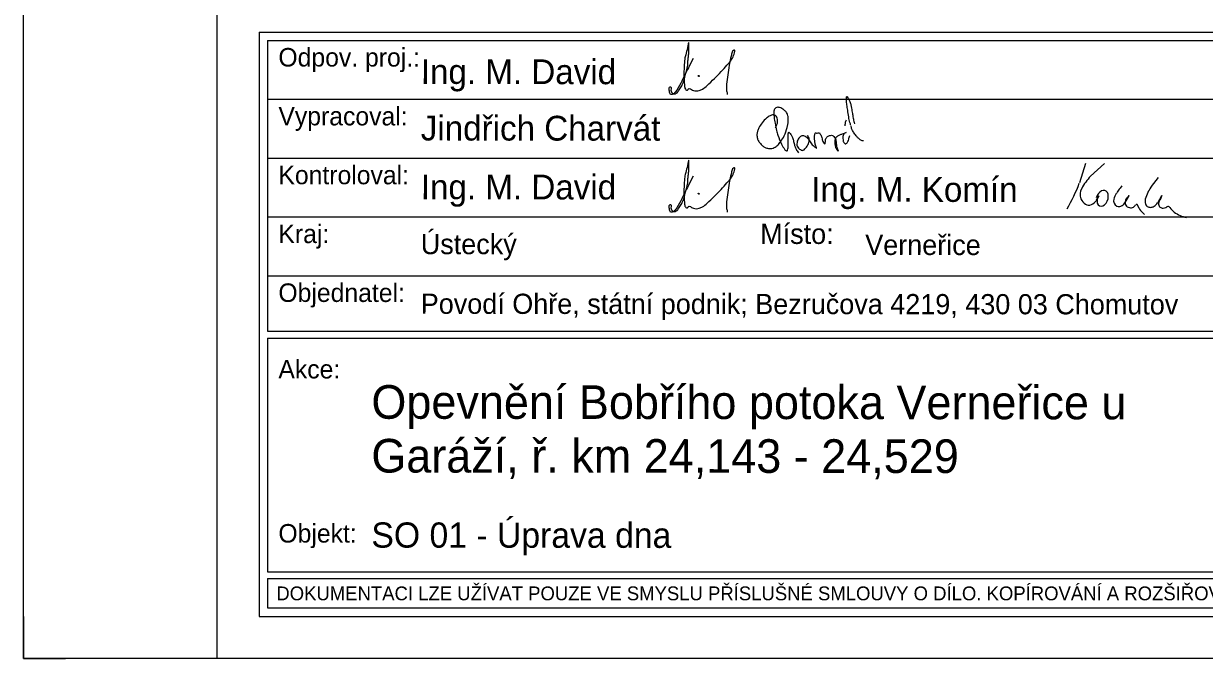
# Model space of a CAD drawing. Extents: x 67.3 to 115.4, y -93.9 to -78.3.
# Drawn here: x 79.77 to 86.79, y -93.93 to -90.16 of the extents above; entities that cross this region are included whole.
import ezdxf

# ---------------------------------------------------------------- set-up
doc = ezdxf.new("R2010")
doc.units = 0
for name, color, linetype in [('07_rozpiska', 7, 'Continuous'), ('07_rámeček', 7, 'Continuous'), ('Default', 7, 'Continuous'), ('Rozpiska + rámeček', 7, 'Continuous')]:
    doc.layers.add(name, color=color, linetype=linetype)

# ---------------------------------------------------------------- blocks, each defined once
blk = doc.blocks.new('Charvat')
at = {"layer": 'Rozpiska + rámeček'}
for points in [[(0.0826, 0.02), (0.0817, 0.0228), (0.0806, 0.0281), (0.0796, 0.0345), (0.0789, 0.0395), (0.0784, 0.0445), (0.0784, 0.0456), (0.0785, 0.0469), (0.0787, 0.0476), (0.0791, 0.0473), (0.0804, 0.0456), (0.0816, 0.0427), (0.0827, 0.0394), (0.0832, 0.0363), (0.0841, 0.0314), (0.0846, 0.0282), (0.0855, 0.0238), (0.086, 0.0216)], [(0.0108, 0.0178), (0.0123, 0.0208), (0.0129, 0.0234), (0.0122, 0.0279), (0.0108, 0.0294), (0.0087, 0.0301), (0.0059, 0.0293), (0.0024, 0.0271), (-0.0017, 0.0225), (-0.0049, 0.0177), (-0.0062, 0.0145), (-0.0067, 0.0115), (-0.0063, 0.0075), (-0.0059, 0.0064), (-0.0039, 0.0034), (-0.0014, 0.0007), (0.001, -0.001), (0.0043, -0.0019), (0.0075, -0.0019), (0.0097, -0.001), (0.0131, 0.0013), (0.0158, 0.0045), (0.0192, 0.0101), (0.022, 0.0182), (0.0223, 0.0193), (0.023, 0.0256), (0.0227, 0.0293), (0.0219, 0.0315), (0.0199, 0.034), (0.017, 0.036), (0.0147, 0.0371), (0.0142, 0.0372), (0.013, 0.0373), (0.0113, 0.0368), (0.0106, 0.0362), (0.0097, 0.0348), (0.0095, 0.0343), (0.0093, 0.0333), (0.0093, 0.0314), (0.0096, 0.0279), (0.0105, 0.0221), (0.012, 0.0151), (0.0133, 0.0108), (0.0166, 0.0023), (0.0195, -0.0026), (0.0202, -0.0035), (0.0214, -0.0042), (0.022, -0.0042), (0.0225, -0.0034), (0.023, -0.0014), (0.0231, 0), (0.0231, 0.0051), (0.0231, 0.0111), (0.0231, 0.0124), (0.0233, 0.0132), (0.0236, 0.0135), (0.024, 0.0133), (0.0254, 0.0115), (0.0268, 0.0092), (0.0279, 0.0059), (0.0289, 0.0018), (0.0298, -0.0012), (0.0315, -0.0041), (0.0327, -0.0059)], [(0.0771, 0.0198), (0.0779, 0.024), (0.0784, 0.0252)], [(0.0428, 0.0062), (0.0417, 0.0075), (0.0401, 0.009), (0.0394, 0.0095), (0.0378, 0.0101), (0.0368, 0.0101), (0.0353, 0.0098), (0.034, 0.0088), (0.0326, 0.0071), (0.0316, 0.0051), (0.0313, 0.0026), (0.0313, 0.0011), (0.0322, -0.0007), (0.0338, -0.0025), (0.0354, -0.0034), (0.0366, -0.0037), (0.0381, -0.0031), (0.0397, -0.0014), (0.0411, 0.0004), (0.0422, 0.0025), (0.043, 0.005), (0.043, 0.0063), (0.0429, 0.0069), (0.0424, 0.0086), (0.0414, 0.0106), (0.0421, 0.009), (0.0433, 0.0053), (0.0444, 0.0034), (0.0458, 0.0017), (0.0476, 0), (0.0497, -0.0015), (0.0498, -0.0016), (0.0499, -0.0016), (0.0499, -0.0014), (0.0492, 0.0003), (0.0487, 0.0022), (0.0482, 0.0055), (0.048, 0.0086), (0.0484, 0.0114), (0.0491, 0.0131), (0.0493, 0.013), (0.0506, 0.0127), (0.0522, 0.0131), (0.0539, 0.0111), (0.0547, 0.0094), (0.0552, 0.0074), (0.0556, 0.0056), (0.0566, 0.0038), (0.058, 0.0025), (0.0582, 0.0031), (0.0585, 0.0057), (0.0589, 0.0076), (0.0593, 0.0083), (0.0604, 0.0095), (0.0616, 0.0102), (0.0632, 0.0106), (0.065, 0.0106), (0.0665, 0.0094), (0.0678, 0.0078), (0.0686, 0.0033), (0.0691, 0.0001), (0.0701, -0.0031), (0.0705, -0.0044), (0.0697, -0.0035), (0.0682, -0.0005), (0.0677, 0.0025), (0.0677, 0.0059), (0.0683, 0.0079), (0.0702, 0.01), (0.0728, 0.0114), (0.0756, 0.0122), (0.0781, 0.0133), (0.0764, 0.0125), (0.0755, 0.0112), (0.0751, 0.0096), (0.0751, 0.0075), (0.0753, 0.005), (0.0753, 0.0048), (0.0758, 0.0038), (0.0766, 0.003), (0.0772, 0.0026), (0.0776, 0.0025), (0.0783, 0.0027), (0.0791, 0.0034), (0.0799, 0.0047), (0.0806, 0.0069), (0.0816, 0.0104)], [(0.0947, 0.0053), (0.0934, 0.0053), (0.0921, 0.0059), (0.0901, 0.0076), (0.0883, 0.0095), (0.0858, 0.0127), (0.0839, 0.0159), (0.0829, 0.0186), (0.0827, 0.0193)]]:
    blk.add_spline(points, degree=3, dxfattribs=at)

msp = doc.modelspace()

# ---------------------------------------------------------------- linework, layer by layer
at = {"layer": '07_rozpiska'}
for points in [[(83.7239, -90.2979), (83.7252, -90.2881), (83.7246, -90.2684), (83.7168, -90.2992), (83.7064, -90.3413), (83.7003, -90.3675), (83.6971, -90.4112), (83.6954, -90.4469), (83.6987, -90.5214), (83.7019, -90.5411), (83.7145, -90.5528), (83.7191, -90.5496), (83.7201, -90.5473), (83.7272, -90.5424), (83.7398, -90.5489), (83.7534, -90.5544), (83.7683, -90.557), (83.7865, -90.5541), (83.8069, -90.5457), (83.8334, -90.5243), (83.8772, -90.4832), (83.9173, -90.442), (83.9513, -90.4035), (83.9789, -90.3701), (83.9938, -90.3371), (83.9973, -90.3209), (83.996, -90.3141), (83.9899, -90.3154), (83.9792, -90.3387), (83.9734, -90.3626), (83.9646, -90.4044), (83.9559, -90.4601), (83.9488, -90.5162), (83.9481, -90.545), (83.9517, -90.5667), (83.9536, -90.5774)], [(83.7178, -90.4031), (83.7197, -90.3772), (83.7223, -90.3546), (83.7243, -90.3303), (83.7239, -90.2979)], [(83.7502, -90.3636), (83.7226, -90.4184), (83.6763, -90.5104), (83.643, -90.5648), (83.6306, -90.5761), (83.6213, -90.5777), (83.6154, -90.5771), (83.6112, -90.5703), (83.6093, -90.5583)], [(83.6093, -90.5583), (83.6073, -90.5466), (83.6083, -90.5389), (83.6132, -90.5324), (83.6167, -90.5317), (83.6187, -90.5437), (83.6193, -90.558), (83.6274, -90.5703), (83.6387, -90.5745), (83.6494, -90.5706), (83.6588, -90.5628), (83.664, -90.556), (83.6792, -90.5317), (83.6854, -90.5201), (83.7013, -90.4738), (83.7178, -90.4031)], [(83.7826, -90.4653), (83.7803, -90.4663), (83.7803, -90.4683), (83.7819, -90.4692), (83.7852, -90.4699), (83.7858, -90.4683), (83.7858, -90.4666), (83.7826, -90.4653)], [(83.7239, -90.9979), (83.7252, -90.9881), (83.7246, -90.9684), (83.7168, -90.9992), (83.7064, -91.0413), (83.7003, -91.0675), (83.6971, -91.1112), (83.6954, -91.1469), (83.6987, -91.2214), (83.7019, -91.2411), (83.7145, -91.2528), (83.7191, -91.2496), (83.7201, -91.2473), (83.7272, -91.2424), (83.7398, -91.2489), (83.7534, -91.2544), (83.7683, -91.257), (83.7865, -91.2541), (83.8069, -91.2457), (83.8334, -91.2243), (83.8772, -91.1832), (83.9173, -91.142), (83.9513, -91.1035), (83.9789, -91.0701), (83.9938, -91.0371), (83.9973, -91.0209), (83.996, -91.0141), (83.9899, -91.0154), (83.9792, -91.0387), (83.9734, -91.0626), (83.9646, -91.1044), (83.9559, -91.1601), (83.9488, -91.2162), (83.9481, -91.245), (83.9517, -91.2667), (83.9536, -91.2774)], [(83.7178, -91.1031), (83.7197, -91.0772), (83.7223, -91.0546), (83.7243, -91.0303), (83.7239, -90.9979)], [(83.7502, -91.0636), (83.7226, -91.1184), (83.6763, -91.2104), (83.643, -91.2648), (83.6306, -91.2761), (83.6213, -91.2777), (83.6154, -91.2771), (83.6112, -91.2703), (83.6093, -91.2583)], [(83.6093, -91.2583), (83.6073, -91.2466), (83.6083, -91.2389), (83.6132, -91.2324), (83.6167, -91.2317), (83.6187, -91.2437), (83.6193, -91.258), (83.6274, -91.2703), (83.6387, -91.2745), (83.6494, -91.2706), (83.6588, -91.2628), (83.664, -91.256), (83.6792, -91.2317), (83.6854, -91.2201), (83.7013, -91.1738), (83.7178, -91.1031)], [(83.7826, -91.1653), (83.7803, -91.1663), (83.7803, -91.1683), (83.7819, -91.1692), (83.7852, -91.1699), (83.7858, -91.1683), (83.7858, -91.1666), (83.7826, -91.1653)]]:
    msp.add_spline(points, degree=3, dxfattribs=at)
at = {"layer": 'Default'}
for p, q in [((86.1487, -91.2049), (86.1631, -91.179)), ((86.3906, -91.2337), (86.4007, -91.251)), ((86.4223, -91.2798), (86.4338, -91.2913))]:
    msp.add_line(p, q, dxfattribs=at)
for points in [[(86.0839, -90.9889), (86.0479, -91.1041)], [(86.1962, -90.9889), (86.1127, -91.0638)], [(86.5159, -91.071), (86.4871, -91.107)], [(86.2999, -91.1214), (86.2898, -91.1358)], [(86.2711, -91.1617), (86.2682, -91.1646)], [(86.3215, -91.2049), (86.3215, -91.2078)], [(86.3359, -91.1905), (86.3431, -91.179), (86.333, -91.1905)], [(86.513, -91.2222), (86.5375, -91.179), (86.5274, -91.2049)], [(86.3186, -91.2222), (86.3186, -91.2222)]]:
    msp.add_lwpolyline(points, dxfattribs=at)
for centre, radius, start, end in [((86.3727, -91.3056), 0.3545, 137.00062, 151.51062), ((85.1146, -90.7574), 0.9948, 329.80858, 339.56815), ((86.125, -91.1722), 0.0732, 150.83631, 201.23374), ((86.5115, -91.3186), 0.288, 140.57196, 146.46893), ((86.7188, -91.2927), 0.2956, 141.11668, 151.43002), ((86.1315, -91.1626), 0.083, 205.78195, 234.22418), ((86.0807, -91.1548), 0.0864, 295.93387, 323.63221), ((86.2259, -91.2204), 0.084, 133.12102, 160.6603), ((86.2051, -91.2127), 0.0529, 142.82783, 193.29225), ((86.3568, -91.2272), 0.1085, 146.31446, 165.71836), ((86.0269, -91.0072), 0.288, 326.31446, 326.46946), ((86.168, -91.1115), 0.1862, 320.58833, 335.16259), ((86.3473, -91.2192), 0.0288, 154.94151, 187.17365), ((86.3745, -91.229), 0.0576, 139.19606, 154.94016), ((86.4996, -91.2134), 0.0617, 158.78845, 195.14726), ((86.6405, -91.2521), 0.2075, 150.931, 162.8917), ((86.5848, -91.2367), 0.0677, 151.17648, 169.00349), ((86.1031, -91.199), 0.0369, 236.98468, 294.62862), ((86.143, -91.3162), 0.0864, 108.04736, 108.08265), ((86.2835, -91.2122), 0.0323, 245.35778, 276.92267), ((86.2765, -91.1981), 0.0475, 283.31943, 318.16716), ((86.3473, -91.2205), 0.0286, 186.45097, 212.31824), ((86.3506, -91.2186), 0.0324, 212.08411, 258.70933), ((86.3522, -91.215), 0.0362, 257.35338, 296.27075), ((86.3458, -91.2108), 0.043, 301.37529, 327.02531), ((86.3869, -91.2371), 0.00576, 26.63136, 150.41952), ((86.4782, -91.2135), 0.0864, 206.63144, 229.82938), ((86.4654, -91.2215), 0.0265, 197.61582, 249.38851), ((86.4718, -91.2028), 0.0463, 250.12564, 275.82035), ((86.4725, -91.214), 0.035, 276.59581, 304.89281), ((86.4307, -91.1655), 0.099, 308.6573, 325.5075), ((86.5479, -91.2279), 0.0297, 172.16185, 218.17447), ((86.547, -91.2195), 0.0349, 229.93747, 256.22885), ((86.5432, -91.2079), 0.0458, 264.36538, 302.31991), ((86.5747, -91.2581), 0.0136, 38.96313, 121.674), ((86.6941, -91.1734), 0.1329, 214.99845, 231.36881), ((86.7307, -91.1078), 0.2073, 234.79421, 256.99308)]:
    msp.add_arc(centre, radius, start, end, dxfattribs=at)
for centre, major_axis, ratio, start_param, end_param in [((86.1846, -91.1946), (0.0152, 0.0459), 0.677007, 2.488228, 7.220838), ((86.2873, -91.2113), (-0.0357, 0.0109), 0.932374, 0, 1.363098)]:
    msp.add_ellipse(centre, major_axis=major_axis, ratio=ratio, start_param=start_param, end_param=end_param, dxfattribs=at)
at = {"layer": 'Rozpiska + rámeček'}
for p, q in [((81.1689, -90.2063), (81.1689, -93.6813)), ((81.1689, -90.2063), (89.7689, -90.2063)), ((81.2189, -90.2563), (81.2189, -91.9863)), ((81.2189, -90.2563), (86.8789, -90.2563)), ((81.2189, -90.6063), (86.8789, -90.6063)), ((81.2189, -90.9563), (86.8789, -90.9563)), ((81.2189, -91.3063), (86.8789, -91.3063)), ((81.2189, -91.6563), (86.8789, -91.6563)), ((81.2189, -91.9863), (86.8789, -91.9863)), ((81.2189, -92.0263), (86.8789, -92.0263)), ((81.2189, -92.0263), (81.2189, -93.4163)), ((81.2189, -93.4163), (86.8789, -93.4163)), ((81.2189, -93.4563), (89.7189, -93.4563)), ((81.2189, -93.4563), (81.2189, -93.6313)), ((81.2189, -93.6313), (89.7189, -93.6313)), ((81.1689, -93.6813), (89.7689, -93.6813))]:
    msp.add_line(p, q, dxfattribs=at)
for points in [[(79.7689, -79.0813), (90.2689, -79.0813), (90.2689, -93.9313), (79.7689, -93.9313)], [(80.9189, -86.5063), (90.0189, -86.5063), (90.0189, -93.9313), (80.9189, -93.9313)]]:
    msp.add_lwpolyline(points, close=True, dxfattribs=at)
msp.add_lwpolyline([(79.7689, -93.6813), (79.7689, -93.9313), (80.0189, -93.9313)], dxfattribs=at)

# ---------------------------------------------------------------- block references
at = {"layer": '07_rámeček', "xscale": 6.250000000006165, "yscale": 6.250000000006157, "rotation": 3.739011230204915e-09}
msp.add_blockref('Charvat', (84.1718, -90.887), dxfattribs=at)

# ---------------------------------------------------------------- texts
at = {"layer": '07_rozpiska'}
for s, height, p in [('Opevnění Bobřího potoka Verneřice u ', 0.2, (81.8369, -92.5061)), ('Garáží, ř. km 24,143 - 24,529', 0.2, (81.8366, -92.8261)), ('SO 01 - Úprava dna', 0.15, (81.8369, -93.2726))]:
    msp.add_text(s, height=height, rotation=359.95393, dxfattribs=at).set_placement(p)
at = {"layer": 'Rozpiska + rámeček'}
for s, height, rotation, p in [('Odpov. proj.:', 0.11, 359.95393, (81.2839, -90.4113)), ('Ing. M. David', 0.147465, 359.95278, (82.1306, -90.5157)), ('Vypracoval:', 0.11, 359.95393, (81.2839, -90.7613)), ('Jindřich Charvát', 0.147465, 359.95278, (82.1306, -90.8513)), ('Kontroloval:', 0.11, 359.95393, (81.2839, -91.1113)), ('Ing. M. David', 0.147465, 359.95278, (82.1306, -91.2013)), ('Ing. M. Komín', 0.147465, 359.95278, (84.4523, -91.2157)), ('Kraj:', 0.11, 359.95393, (81.2839, -91.4613)), ('Místo:', 0.12, 359.95393, (84.1489, -91.4663)), ('Ústecký', 0.12, 359.95393, (82.1306, -91.5273)), ('Verneřice', 0.12, 359.95278, (84.7738, -91.5321)), ('Objednatel:', 0.11, 359.95393, (81.2839, -91.8113)), ('Povodí Ohře, státní podnik; Bezručova 4219, 430 03 Chomutov', 0.12, 359.95278, (82.1306, -91.8821)), ('Akce:', 0.11, 359.95393, (81.2839, -92.2663)), ('Objekt:', 0.11, 359.95393, (81.2839, -93.2424))]:
    msp.add_text(s, height=height, rotation=rotation, dxfattribs=at).set_placement(p)
msp.add_text('DOKUMENTACI LZE UŽÍVAT POUZE VE SMYSLU PŘÍSLUŠNÉ SMLOUVY O DÍLO. KOPÍROVÁNÍ A ROZŠIŘOVÁNÍ POUZE PO PŘEDCHOZÍM SOUHLASU  AZ CONSULT spol. s. r.o.', height=0.0822563, dxfattribs=at).set_placement((81.2718, -93.5859))

doc.saveas('drawing.dxf')
